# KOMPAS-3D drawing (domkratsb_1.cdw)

Views: Вид 1
Referenced files: Чертеж1.cdw
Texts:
  Домкрат грузоподъемностью Q=32 kH
  Текст на чертеже
  Размерные надписи
  Шероховатость
  Линия-выноска #1
  Линия-выноска #2
  Линия-выноска #3
  Отклонения формы и база
  Заголовок таблицы
  Ячейка таблицы
  Стрелка вида
  Обозначение изменения
  Фигурная скобка
  Номер узла
  Марка координационной оси
  VRCB
  Выносная надпись
  Обозначение узла
  Марка/позиционное обозначение с линией-выноской
  Марка/позиционное обозначение на линии
  Марка/позиционное обозначение без линии-выноски
  Symbol type A
  отверстия  8Н7
  сверлить, развернуть после запресовки
  гайки 2 в корпус 1
  Кв.32Х4-7ZA/7h
  Домкрат грузоподъемностью
Dimensions and other numbers on the sheet: 61 00 T 7 СБ; 7; 165; 32.4; 60; 50; 35H9/d9; 24.8; 6.8; 2; 52; 35 LO/Js6; 2 отв.; 8; 10; 1; 5; 3; 4; 52 LO/js6; 190; 6; 15; 1:2; 0; 9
